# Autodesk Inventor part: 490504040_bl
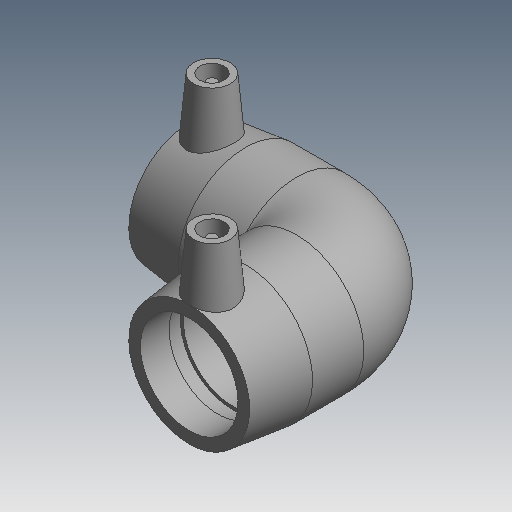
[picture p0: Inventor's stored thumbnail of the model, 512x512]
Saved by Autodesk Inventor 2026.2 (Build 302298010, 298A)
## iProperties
Created: 2017-06
Part Number: 490504040_bl
Material: Generic
Description: PLASSON 90° ELBOW 40
Document SubType Name: Modeling
Designer: KIM
Mass: 55.0731 g
Surface Area: 148.067 cm^2
Volume: 55.0731 cm^3
Density: 1 g/cm^3
Appearance: Default
Author: KIM
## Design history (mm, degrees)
derived "490504 -20-75.ipt"
feature "Solid1::490504 -20-75.ipt" dims "ScaleForDerivedMember" = 10
tag "TaggingFeature1"
body "Solid1"
other parameters: "d2" = 55 [user parameter], "d4" = 23 [user parameter], "d5" = 49.5 [user parameter], "d8" = 168 deg [user parameter], "d10" = 17.6 [user parameter], "d11" = 5.86667 [user parameter], "d14" = 17.6296 [user parameter], "d19" = 3.52592 [user parameter], "d20" = 168 deg [user parameter], "d22" = 50.6 [user parameter], "d23" = 55 [user parameter], "d24" = 49.082 [user parameter], "d29" = 47 [user parameter], "d30" = 15 [user parameter], "d31" = 55.2 [user parameter], "d34" = 5 deg [user parameter], "d35" = 15 [user parameter], "d39" = 5 deg [user parameter], "d41" = 4 [user parameter], "d42" = 14 [user parameter], "d43" = 0 [user parameter], "d45" = 4 [user parameter], "d46" = 14 [user parameter], "d47" = 0 [user parameter], "d50" = 34 [user parameter], "d51" = 17.6 [user parameter], "d52" = 44 [user parameter], "d54" = 90 deg [user parameter], "d67" = 45 deg [user parameter], "d71" = 90 deg [user parameter], "d75" = 2.75 [user parameter], "d82" = 45 deg [user parameter], "d83" = 44 [user parameter], "d84" = 49.5 [user parameter], "d87" = 90 deg [user parameter], "d90" = 44 [user parameter], "d91" = 0 [user parameter], "d92" = 44 [user parameter], "d93" = 0 [user parameter], "d94" = 90 deg [user parameter], "d101" = 3 [user parameter], "d102" = 0 [user parameter], "d103" = 3 [user parameter], "d104" = 0 [user parameter], "d105" = 12.76 [user parameter], "d106" = 3.19 [user parameter], "d110" = 24.2 [user parameter], "d111" = 92 [user parameter], "d112" = 92 [user parameter], "d113" = 92 [user parameter], "d114" = 92 [user parameter], "L_" = 92 [user parameter], "L_1" = 44 [user parameter], "D_" = 55 [user parameter], "A_" = 47 [user parameter], "d_2" = 12 [user parameter]
